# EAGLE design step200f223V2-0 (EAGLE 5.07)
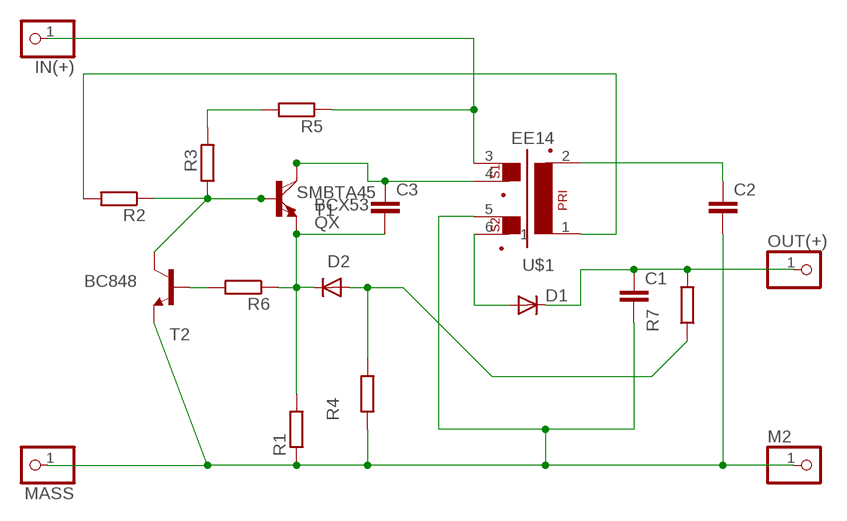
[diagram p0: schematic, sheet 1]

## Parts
C1  C-EU050-025X075  [C050-025X075]
C2  C-EUC0805  [C0805]
C3  C-EU025-024X044  [C025-024X044]
D1  DIODE-SMA-DO214  [SMA-DO214AC]
D2  DIODE-MINIMELF  [MINIMELF]
IN(+)  PINHD-1X11MM6  [1X1MM8]
M2  PINHD-1X11MM6  [1X1MM8]
MASS  PINHD-1X11MM6  [1X1MM8]
OUT(+)  PINHD-1X11MM6  [1X1MM8]
QX  BCX53  [SOT223]
R1  R-EU_R1206  [R1206]
R2  R-EU_R0805  [R0805]
R3  R-EU_R1206  [R1206]
R4  R-EU_R0805  [R0805]
R5  R-EU_R1206  [R1206]
R6  R-EU_R0805  [R0805]
R7  R-EU_R0805  [R0805]
T1  SMBTA45  BC848  [SOT23]
T2  BC848  [SOT23]
U$1  EE14  [EE14]

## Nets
A: D1.A U$1.6
B1C2: QX.1(B) R2.1 R3.1 T1.B T2.C
C1: C3.1 QX.2(C) T1.C U$1.4
EB: C3.2 D2.C QX.3(E) R1.2 R6.1 T1.E
N$1: R3.2 R5.2
N$2: R6.2 T2.B
N$3: D2.A R4.2 R7.1
N$4: R2.2 U$1.1
N$6: C2.1 U$1.2
V+: IN(+).1 R5.1 U$1.3
V-: C1.2 C2.2 M2.1 MASS.1 R1.1 R4.1 T2.E U$1.5
VOUT+: C1.1 D1.K(C) OUT(+).1 R7.2

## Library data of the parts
C1-C3 = rcl:C-EU: CAPACITOR, European symbol
D1 D2 = diode:DIODE-: DIODE
IN(+) M2 MASS OUT(+) = pinhead:PINHD-1X1: PIN HEADER
QX = transistor-power:BCX53
R1-R7 = rcl:R-EU_: RESISTOR, European symbol
T1 T2 = transistor:BC848: NPN TRANSISTOR
U$1 = trafo:EE14

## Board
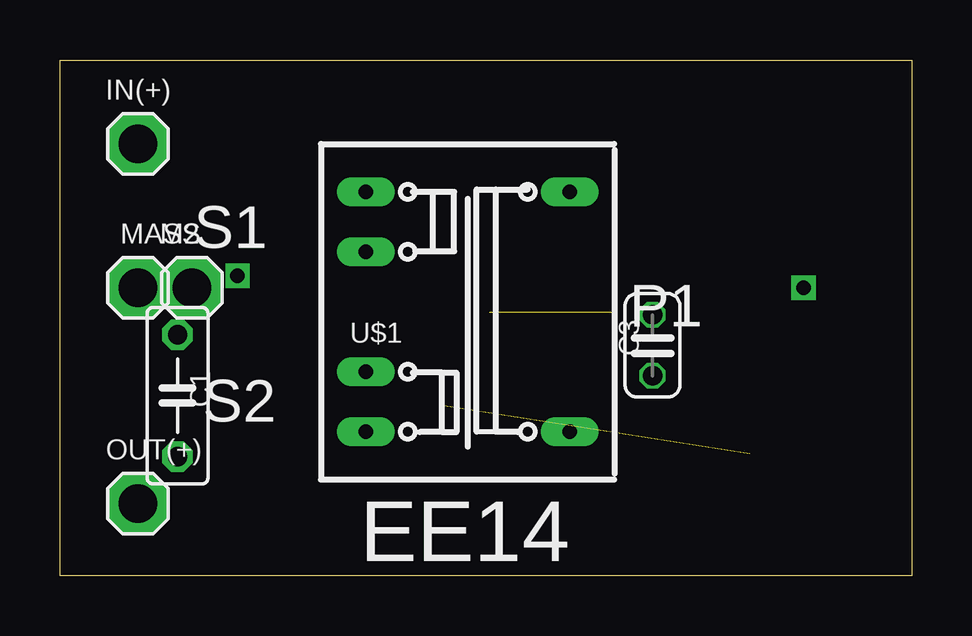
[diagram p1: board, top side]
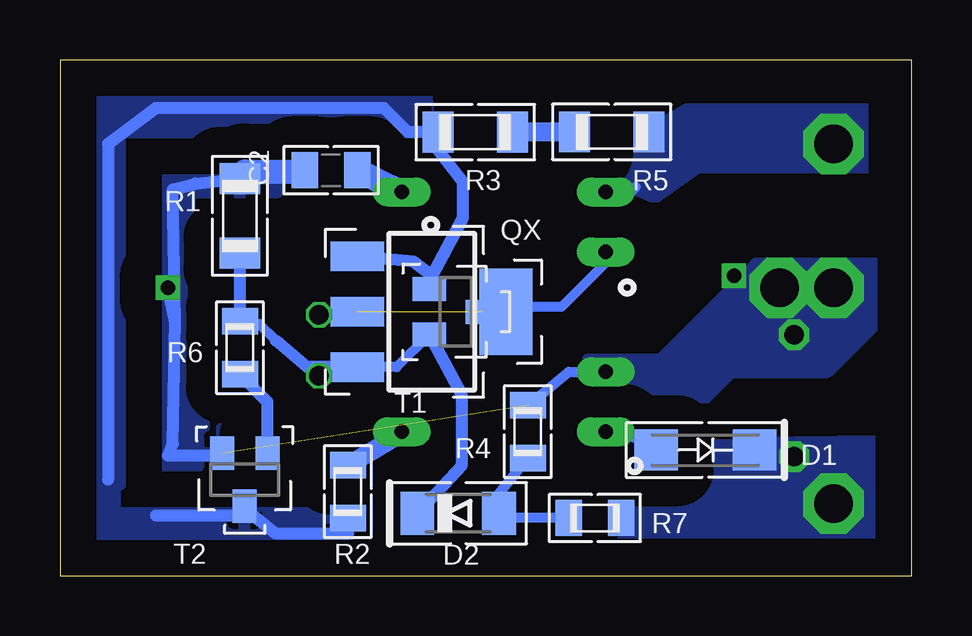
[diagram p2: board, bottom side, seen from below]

Size 35.5 x 21.5 mm. Coordinates in mm from the lower left corner, seen from the top.
Outline: 0,21.5 35.5,21.5 35.5,0 0,0 0,21.5
Copper layers (1*16): Top 0.035mm / dielectric 1.5mm / Bottom 0.035mm
Design rules "default *": minimum track width 10mil, minimum drill 20mil, track to track 8mil, track to pad 8mil, pad to pad 8mil, via to via 8mil, smd to smd 8mil, copper to edge 40mil, drill to drill 8mil, minimum pad ring 5mil, minimum via ring 8mil, stop-mask expansion 4mil, vias tented up to drill 0mil, thermal gap 10mil

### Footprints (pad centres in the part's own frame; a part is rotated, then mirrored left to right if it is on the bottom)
C050-025X075 = drill 0.8 pad 1.27 octagon: 1 -2.54,0; 2 2.54,0
C0805 = smd 1.1 x 1.5: 1 -1.1,0; 2 1.1,0
C025-024X044 = drill 0.813 octagon: 1 -1.27,0; 2 1.27,0
SMA-DO214AC = smd 1.8 x 1.7: A 2.05,-0.127; K -2.05,-0.127
MINIMELF = smd 1.4 x 1.8: A 1.7,0; C -1.7,0
1X1MM8 = drill 1.6 pad 2.54 octagon: 1 0,0
SOT223 = smd 1.219 x 2.235: 1 -2.311,-3.099; 2 0,-3.099; 3 2.311,-3.099 | smd 3.6 x 2.2: 4 0,3.099
R1206 = smd 1.3 x 1.7: 1 -1.55,0; 2 1.55,0
R0805 = smd 1.1 x 1.5: 1 -1.1,0; 2 1.1,0
SOT23 = smd 1 x 1.4: B -0.95,-1.1; C 0,1.1; E 0.95,-1.1
EE14 = drill 0.6 pad 1.2 long: 1 4.25,-5; 2 4.25,5; 3 -4.25,5; 4 -4.25,2.5; 5 -4.25,-2.5; 6 -4.25,-5

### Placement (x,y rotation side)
C1  4.9,7.5 90 top
C2  24.2,16.9 180 bottom
C3  24.7,9.6 270 top
D1  8.6,5.11 180 bottom
D2  18.9,2.6 0 bottom
IN(+)  3.25,18 0 top
M2  5.5,12 0 top
MASS  3.25,12 0 top
OUT(+)  3.25,3 0 top
QX  20,11 270 bottom
R1  28,15 270 bottom
R2  23.5,3.5 90 bottom
R3  18.19,18.49 0 bottom
R4  16,6 270 bottom
R5  12.5,18.5 180 bottom
R6  28,9.5 270 bottom
R7  13.2,2.4 0 bottom
T1  19,11 270 bottom
T2  27.8,4 180 bottom
U$1  17,11 0 top

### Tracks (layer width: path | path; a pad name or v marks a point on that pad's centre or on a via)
A
  Bottom 0.406: U$1.6 12.01,6 D1.A
B1C2
  Bottom 0.406: 19.74,17.74 R3.1
  Bottom 0.5: 19.74,17.74 18.7,16.4 18.7,14.9 20,12.5 | 20,12.5 20.79,13.1 QX.1 | R3.1 20.99,18.49 22,19.5 31.5,19.5 33.5,18 33.5,4 | 31.5,2.5 28.2,2.5 T2.C 27.8,2.8 26.5,1.75 23.5,1.75 R2.1 | T1.B 20.1,12.4 20,12.5
  pour Bottom (isolate 1.5): 20.2,20 34.4,20 34.4,1.1 23.3,1.1 23.3,1.2 23.2,1.2 23.2,2.6 33.2,2.6 33.2,3.8 33,3.8 33,18.5 20.1,18.5
C1  (1 unrouted)
  Bottom 0.406: U$1.4 12.75,13.05 14.6,11.2 17.7,11.2 T1.C 17.1,11 17,11.1 | C3.1 23.23,10.87 QX.2
EB
  Bottom 0.406: 27.9,10.5 27.2,10.5 26.5,9.8 | QX.3 21.46,8.69 T1.E | C3.2 24.16,8.33 23.8,8.69
  Bottom 0.5: R6.1 28,10.5 | R6.1 R1.2 | QX.3 23.8,8.69 25.19,8.69 26.5,9.8 | 27.9,10.5 R6.1 | T1.E 18.75,7.53 18.75,4.6 D2.C
N$1
  Bottom 0.8: R5.2 15.63,18.5 R3.2
N$2
  Bottom 0.5: T2.B 26.85,7.25 R6.2
N$3
  Bottom 0.406: R7.1 17,2.4 D2.A 17.2,3.4 R4.2
N$4
  Bottom 0.8: R2.2 22,5.5 U$1.1
N$6
  Bottom 1: C2.1 21.7,16.2 U$1.2
V+
  Bottom 0.406: U$1.3 11.7,16 11.5,16.2
  pour Bottom (isolate 1.8, rank 4, no thermals): 0.96,20.54 7.46,20.54 12.1,17.9 13.1,18.04 13.5,15.1 11.43,15.24 8.89,17.04 0.96,17.04
V-  (via drill 0.6)  (1 unrouted)
  Bottom 0.406: U$1.5 14.3,8.5 R4.1
  Bottom 0.5: 30.7,10.6 30.8,5.5 31,5 28.85,5 T2.E | 30.7,10.6 30.8,16.1 29.85,16.35 R1.1 27.8,16.85 | 30.7,10.6 v31,12
  Bottom 1: 27.8,16.85 25.75,16.85 25.6,16.8 C2.2
  other vias: 7.4,12.5
  pour Bottom (isolate 1.422, no thermals): 1.5,13 6.5,13 10.5,9 13.5,9 13.5,7 9,7 7.5,8.5 3.5,8.5 1.5,10.5
  pour Bottom (isolate 1.5, rank 2): 23.5,18.3 30.6,18.3 31.5,16.3 31.5,4.7 31,4.4 28.6,4.5 28.5,4.4 28.5,6.5 28.6,6.6 29.4,6.6 30.1,7.3 30.1,15.9 30,16 26.4,16 25.7,16.7 23.8,16.7 23.5,17
VOUT+
  pour Bottom (isolate 1.5, rank 3, no thermals): 1.4,5.6 10,5.5 13.4,4.8 16.1,1.8 1.4,1.8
